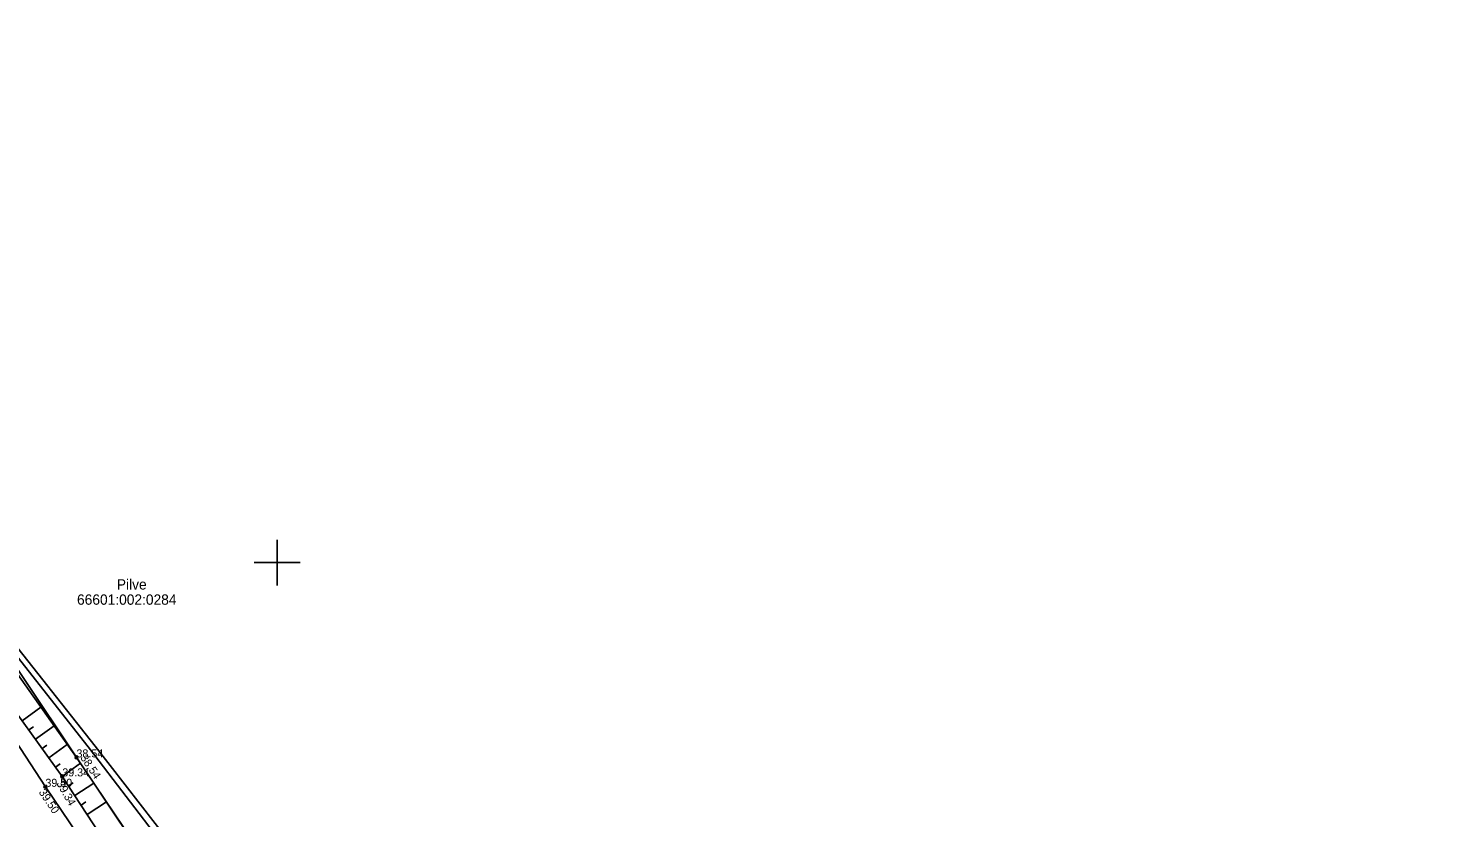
# Model space of a CAD drawing. Extents: x 627548 to 628052, y 6467984 to 6468802.
# Drawn here: x 627778.2 to 627901.6, y 6468527.7 to 6468596.8 of the extents above; entities that cross this region are included whole.
import ezdxf

# ---------------------------------------------------------------- set-up
doc = ezdxf.new("R2010")
doc.units = 0
for name, color, linetype in [('KORGUS-EH2000', 7, 'Continuous'), ('KPKAABEL', 7, 'Continuous'), ('MOOTKORG-EH2000', 7, 'Continuous'), ('MOOTMPUNKT', 7, 'Continuous'), ('MPKAABEL', 7, 'Continuous'), ('PIIR', 7, 'Continuous'), ('RELJEEF', 7, 'Continuous'), ('TEE', 7, 'Continuous'), ('VORK', 7, 'Continuous')]:
    doc.layers.add(name, color=color, linetype=linetype)

msp = doc.modelspace()

# ---------------------------------------------------------------- linework, layer by layer
at = {"layer": 'KPKAABEL'}
msp.add_lwpolyline([(627774.13, 6468545.73), (627783.66, 6468533.61), (627793.04, 6468521.37)], dxfattribs=at)
at = {"layer": 'MOOTMPUNKT'}
for centre in [(627782.44, 6468532.95), (627781.2, 6468531.29), (627779.72, 6468530.38)]:
    msp.add_circle(centre, 0.125, dxfattribs=at)
at = {"layer": 'MPKAABEL'}
msp.add_lwpolyline([(627775.61, 6468546.29), (627774.98, 6468546.79), (627774.72, 6468546.18), (627774.69, 6468545.9), (627776.11, 6468544.04), (627784.09, 6468533.94), (627791.95, 6468523.77), (627800.68, 6468512.58), (627810.04, 6468500.51), (627813.46, 6468495.35), (627814.99, 6468492.48), (627821.28, 6468482.3), (627827.85, 6468471.01), (627838.64, 6468452.75), (627843.99, 6468447.78), (627852.33, 6468430.34), (627859.23, 6468424.97)], dxfattribs=at)
at = {"layer": 'PIIR'}
msp.add_line((627739.66, 6468596.76), (627806.32, 6468497.36), dxfattribs=at)
at = {"layer": 'RELJEEF'}
for p, q in [((627777.69, 6468536.16), (627779.32, 6468537.34)), ((627778.27, 6468535.35), (627778.68, 6468535.64)), ((627778.86, 6468534.54), (627780.48, 6468535.71)), ((627779.44, 6468533.73), (627779.85, 6468534.02)), ((627780.02, 6468532.91), (627781.64, 6468534.08)), ((627780.61, 6468532.1), (627781.01, 6468532.4)), ((627781.19, 6468531.29), (627782.78, 6468532.44)), ((627781.74, 6468530.45), (627782.16, 6468530.73)), ((627782.29, 6468529.62), (627783.95, 6468530.7)), ((627782.84, 6468528.78), (627783.26, 6468529.06)), ((627783.38, 6468527.94), (627785.07, 6468529.05))]:
    msp.add_line(p, q, dxfattribs=at)
for points in [[(627773.76, 6468549.46), (627771.3, 6468547.15), (627771.11, 6468545.29), (627781.2, 6468531.29), (627796.85, 6468507.37), (627811.93, 6468482.61), (627825.93, 6468458.24), (627843.64, 6468425.49), (627854.71, 6468402.3), (627862.1, 6468385.4), (627866.29, 6468377.39), (627871.18, 6468377.94)], [(627772.37, 6468547.14), (627782.44, 6468532.95), (627799.73, 6468507.29), (627814.06, 6468485.68), (627830.01, 6468459.01), (627845.39, 6468427.25), (627850.56, 6468416.94), (627856.09, 6468405.16), (627864.81, 6468385.75), (627868.21, 6468378.88), (627870.92, 6468379.12)]]:
    msp.add_lwpolyline(points, dxfattribs=at)
at = {"layer": 'TEE'}
msp.add_lwpolyline([(627773.88, 6468550.47), (627771.33, 6468547.78), (627770.18, 6468544.97), (627779.72, 6468530.38), (627790.19, 6468514.89), (627795.6, 6468506.27), (627810.36, 6468482.16), (627820.25, 6468465.61), (627824.79, 6468457.18), (627842.02, 6468424.68), (627853.22, 6468402.01), (627861.19, 6468384.86), (627867.23, 6468371.17), (627873.07, 6468356.38), (627889.26, 6468318.91), (627892.45, 6468311.43), (627896.87, 6468301.52), (627899.4, 6468301.54), (627901.63, 6468302.36)], dxfattribs=at)
at = {"layer": 'VORK'}
for p, q in [((627800, 6468552), (627800, 6468548)), ((627798, 6468550), (627802, 6468550))]:
    msp.add_line(p, q, dxfattribs=at)

# ---------------------------------------------------------------- texts
at = {"layer": 'KORGUS-EH2000'}
for s, rotation, p in [('38.54', 303.967, (627782.74, 6468532.92)), ('39.50', 303.6771, (627779.11, 6468529.9)), ('39.34', 299.7574, (627780.66, 6468530.67))]:
    msp.add_text(s, height=0.7, rotation=rotation, dxfattribs=at).set_placement(p)
at = {"layer": 'MOOTKORG-EH2000'}
for s, p in [('38.54', (627782.44, 6468532.95)), ('39.50', (627779.72, 6468530.38)), ('39.34', (627781.2, 6468531.29))]:
    msp.add_text(s, height=0.7, dxfattribs=at).set_placement(p)
at = {"layer": 'PIIR'}
for s, p in [('Pilve', (627785.97, 6468547.64)), ('66601:002:0284', (627782.49, 6468546.31))]:
    msp.add_text(s, height=0.9, dxfattribs=at).set_placement(p)

doc.saveas('drawing.dxf')
